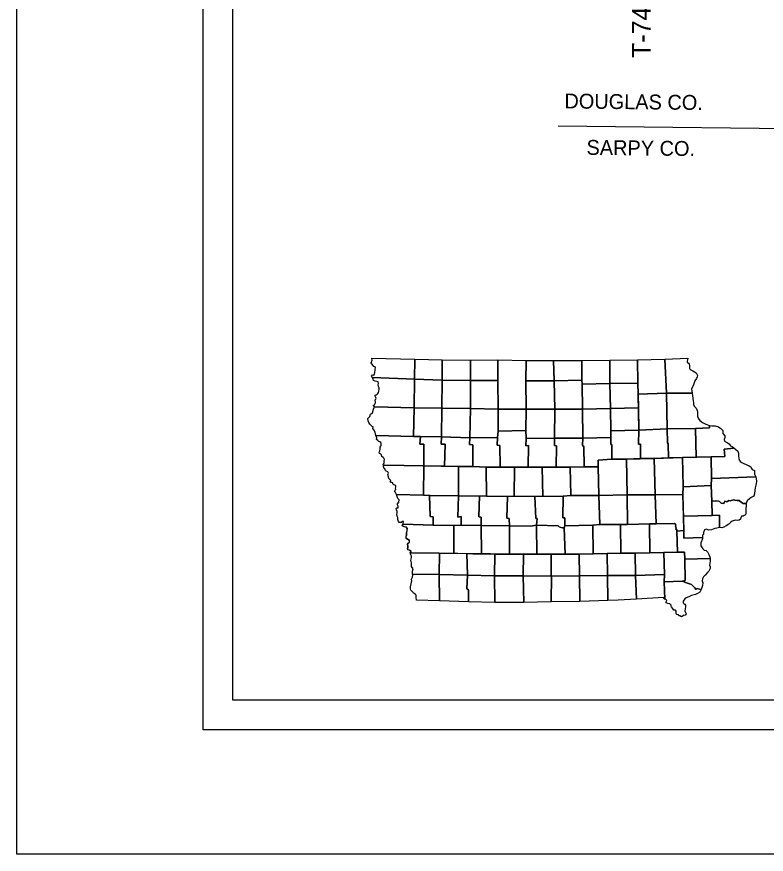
# Model space of a CAD drawing. Extents: x -132.8 to -73.3, y -60 to -26.
# Drawn here: x -132.82 to -126.79, y -60.01 to -53.27 of the extents above; entities that cross this region are included whole.
import ezdxf

# ---------------------------------------------------------------- set-up
doc = ezdxf.new("R2010")
doc.units = 0
for name, color, linetype in [('tdCoCoBndryPart', 7, 'Continuous'), ('tdCoCoBndryTxt', 7, 'Continuous'), ('tdCoFrame', 7, 'Continuous'), ('tdCoPlotFrame', 7, 'Continuous'), ('tdCoTitleBlock', 7, 'Continuous'), ('tdCoTwpRngTxt', 7, 'Continuous')]:
    doc.layers.add(name, color=color, linetype=linetype)

msp = doc.modelspace()

# ---------------------------------------------------------------- linework, layer by layer
at = {"layer": 'tdCoCoBndryPart'}
msp.add_lwpolyline([(-126.151, -54.1793), (-128.4616, -54.1519)], dxfattribs=at)
at = {"layer": 'tdCoFrame'}
for points in [[(-131.3199, -27.0113), (-77.8199, -27.0113), (-77.8199, -59.0113), (-131.3199, -59.0113)], [(-131.0799, -27.2513), (-78.0599, -27.2513), (-78.0599, -58.7713), (-131.0799, -58.7713)]]:
    msp.add_lwpolyline(points, close=True, dxfattribs=at)
at = {"layer": 'tdCoPlotFrame'}
msp.add_lwpolyline([(-132.8199, -26.0113), (-76.8199, -26.0113), (-76.8199, -60.0113), (-132.8199, -60.0113)], close=True, dxfattribs=at)
at = {"layer": 'tdCoTitleBlock'}
for points in [[(-129.9621, -56.0202), (-129.615, -56.0286), (-129.6188, -56.1889), (-129.9564, -56.1753), (-129.9634, -56.1641), (-129.9572, -56.1529), (-129.9463, -56.1549), (-129.9407, -56.1472), (-129.9372, -56.1349), (-129.9334, -56.1143), (-129.931, -56.0912), (-129.9384, -56.0884), (-129.9454, -56.0856), (-129.9542, -56.0744), (-129.9659, -56.0559), (-129.9585, -56.0363)], [(-129.615, -56.0286), (-129.3939, -56.0332), (-129.3945, -56.1956), (-129.6188, -56.1889)], [(-129.3939, -56.0332), (-129.1665, -56.036), (-129.1671, -56.1977), (-129.3945, -56.1956)], [(-129.1665, -56.036), (-128.9476, -56.0339), (-128.9481, -56.1998), (-129.1671, -56.1977)], [(-128.9476, -56.0339), (-128.7187, -56.0388), (-128.7204, -56.2016), (-128.718, -56.4287), (-128.945, -56.4287), (-128.9481, -56.1998)], [(-128.7187, -56.0388), (-128.4984, -56.0388), (-128.4944, -56.2026), (-128.7204, -56.2016)], [(-128.4984, -56.0388), (-128.271, -56.0374), (-128.2709, -56.196), (-128.4944, -56.2026)], [(-128.271, -56.0374), (-128.0467, -56.0354), (-128.0445, -56.2226), (-128.2676, -56.2296), (-128.2709, -56.196)], [(-128.0467, -56.0354), (-127.8239, -56.0319), (-127.8213, -56.2205), (-128.0445, -56.2226)], [(-127.8239, -56.0319), (-127.6021, -56.0263), (-127.5905, -56.3021), (-127.8165, -56.3087), (-127.8213, -56.2205)], [(-127.6021, -56.0263), (-127.4186, -56.0187), (-127.4211, -56.0331), (-127.4231, -56.0422), (-127.4224, -56.0513), (-127.4133, -56.0607), (-127.408, -56.0677), (-127.4037, -56.0782), (-127.4051, -56.1009), (-127.3987, -56.1111), (-127.3773, -56.1201), (-127.3632, -56.1288), (-127.3506, -56.1368), (-127.3439, -56.147), (-127.3407, -56.1595), (-127.3414, -56.1708), (-127.3487, -56.1841), (-127.3606, -56.2027), (-127.3741, -56.2409), (-127.3892, -56.2664), (-127.382, -56.2997), (-127.5905, -56.3021)], [(-129.9564, -56.1753), (-129.6188, -56.1889), (-129.6213, -56.4192), (-129.9406, -56.4097), (-129.9477, -56.4062), (-129.9491, -56.3982), (-129.94, -56.3936), (-129.9333, -56.3848), (-129.9309, -56.3754), (-129.9316, -56.3673), (-129.9355, -56.3628), (-129.9345, -56.3554), (-129.9282, -56.3502), (-129.9257, -56.3418), (-129.9303, -56.3362), (-129.9332, -56.326), (-129.9342, -56.3159), (-129.9258, -56.3138), (-129.9188, -56.3092), (-129.9129, -56.3046), (-129.9069, -56.2959), (-129.9049, -56.2839), (-129.9017, -56.2699), (-129.9018, -56.2591), (-129.9078, -56.2479), (-129.9092, -56.2332), (-129.9075, -56.2238), (-129.9107, -56.2094), (-129.9202, -56.2066), (-129.9349, -56.2042), (-129.9476, -56.1983), (-129.9504, -56.1892)], [(-129.6188, -56.1889), (-129.3945, -56.1956), (-129.3974, -56.422), (-129.6213, -56.4192)], [(-129.3945, -56.1956), (-129.1671, -56.1977), (-129.1679, -56.4245), (-129.3974, -56.422)], [(-129.1671, -56.1977), (-128.9481, -56.1998), (-128.945, -56.4287), (-129.1679, -56.4245)], [(-128.7204, -56.2016), (-128.4944, -56.2026), (-128.4892, -56.4305), (-128.718, -56.4287)], [(-128.4944, -56.2026), (-128.2709, -56.196), (-128.2676, -56.2296), (-128.2649, -56.4294), (-128.4892, -56.4305)], [(-128.2676, -56.2296), (-128.0445, -56.2226), (-128.0397, -56.4249), (-128.2649, -56.4294)], [(-128.0445, -56.2226), (-127.8213, -56.2205), (-127.8165, -56.3087), (-127.8151, -56.42), (-128.0397, -56.4249)], [(-127.8165, -56.3087), (-127.5905, -56.3021), (-127.5844, -56.5887), (-127.8114, -56.5981)], [(-127.5905, -56.3021), (-127.382, -56.2997), (-127.3752, -56.3637), (-127.372, -56.3791), (-127.373, -56.3921), (-127.3663, -56.4064), (-127.3512, -56.4228), (-127.3424, -56.4392), (-127.3392, -56.4542), (-127.3402, -56.4693), (-127.3387, -56.4861), (-127.3345, -56.5022), (-127.3207, -56.521), (-127.2986, -56.5378), (-127.2715, -56.5496), (-127.242, -56.5607), (-127.2419, -56.5789), (-127.357, -56.5863), (-127.5844, -56.5887)], [(-129.9406, -56.4097), (-129.6213, -56.4192), (-129.6252, -56.6492), (-129.9298, -56.6407), (-129.9341, -56.6148), (-129.9447, -56.597), (-129.9528, -56.5865), (-129.9497, -56.5728), (-129.9584, -56.568), (-129.9764, -56.5502), (-129.9863, -56.5372), (-129.9905, -56.5229), (-129.993, -56.5058), (-129.9867, -56.4966), (-129.9783, -56.4886), (-129.9714, -56.469), (-129.9567, -56.4584), (-129.9487, -56.429)], [(-129.6213, -56.4192), (-129.3974, -56.422), (-129.4006, -56.6524), (-129.5694, -56.6494), (-129.6252, -56.6492)], [(-129.3974, -56.422), (-129.1679, -56.4245), (-129.1714, -56.659), (-129.4006, -56.6524)], [(-129.1679, -56.4245), (-128.945, -56.4287), (-128.9431, -56.6055), (-128.9486, -56.658), (-129.1714, -56.659)], [(-128.945, -56.4287), (-128.718, -56.4287), (-128.7214, -56.6013), (-128.9431, -56.6055)], [(-128.718, -56.4287), (-128.4892, -56.4305), (-128.4906, -56.665), (-128.7177, -56.6653), (-128.7214, -56.6013)], [(-128.4892, -56.4305), (-128.2649, -56.4294), (-128.2629, -56.6639), (-128.4899, -56.6643)], [(-128.2649, -56.4294), (-128.0397, -56.4249), (-128.0381, -56.6044), (-128.0373, -56.658), (-128.2629, -56.6639)], [(-128.0397, -56.4249), (-127.8151, -56.42), (-127.8114, -56.5981), (-128.0381, -56.6044)], [(-128.9431, -56.6055), (-128.7214, -56.6013), (-128.7177, -56.6653), (-128.7217, -56.7238), (-128.7, -56.7209), (-128.7016, -56.8952), (-128.8142, -56.8956), (-128.9279, -56.8931), (-128.9302, -56.7216), (-128.9516, -56.7182), (-128.9486, -56.658)], [(-128.0381, -56.6044), (-127.8114, -56.5981), (-127.8153, -56.7105), (-127.7995, -56.7112), (-127.7992, -56.8267), (-127.9118, -56.8316), (-128.029, -56.8316), (-128.0294, -56.715), (-128.0385, -56.7147), (-128.0373, -56.658)], [(-127.8114, -56.5981), (-127.5844, -56.5887), (-127.5813, -56.7), (-127.5746, -56.7094), (-127.5722, -56.8225), (-127.688, -56.826), (-127.7992, -56.8267), (-127.7995, -56.7112), (-127.8153, -56.7105)], [(-127.5844, -56.5887), (-127.357, -56.5863), (-127.3494, -56.8155), (-127.5722, -56.8225), (-127.5746, -56.7094), (-127.5813, -56.7)], [(-127.357, -56.5863), (-127.2419, -56.5789), (-127.242, -56.5607), (-127.223, -56.5634), (-127.1964, -56.5627), (-127.1693, -56.5713), (-127.151, -56.586), (-127.1366, -56.6006), (-127.1369, -56.6258), (-127.1189, -56.645), (-127.1203, -56.6587), (-127.1259, -56.6741), (-127.1227, -56.687), (-127.097, -56.7003), (-127.0858, -56.7086), (-127.0738, -56.724), (-127.0601, -56.7309), (-127.0446, -56.7442), (-127.126, -56.7518), (-127.1206, -56.8113), (-127.2308, -56.8137), (-127.3494, -56.8155)], [(-129.9298, -56.6407), (-129.6252, -56.6492), (-129.5694, -56.6494), (-129.5762, -56.7106), (-129.5426, -56.7102), (-129.5421, -56.8859), (-129.8607, -56.8813), (-129.8667, -56.8855), (-129.8709, -56.8743), (-129.8636, -56.8652), (-129.8601, -56.8606), (-129.8608, -56.8522), (-129.8612, -56.8421), (-129.8594, -56.8361), (-129.8619, -56.826), (-129.8711, -56.8197), (-129.8806, -56.811), (-129.8841, -56.7977), (-129.8908, -56.7904), (-129.8985, -56.7851), (-129.9031, -56.7767), (-129.9007, -56.7701), (-129.8972, -56.7645), (-129.8951, -56.7533), (-129.893, -56.7428), (-129.8938, -56.7347), (-129.8889, -56.7277), (-129.8868, -56.7203), (-129.8868, -56.7063), (-129.8897, -56.6973), (-129.896, -56.6938), (-129.9051, -56.6886), (-129.9136, -56.6816), (-129.9227, -56.6732), (-129.9206, -56.6592)], [(-129.5694, -56.6494), (-129.4006, -56.6524), (-129.4029, -56.7119), (-129.372, -56.7111), (-129.3768, -56.8889), (-129.5421, -56.8859), (-129.5426, -56.7102), (-129.5762, -56.7106)], [(-129.4006, -56.6524), (-129.1714, -56.659), (-129.1748, -56.7143), (-129.1495, -56.7156), (-129.1483, -56.8903), (-129.2624, -56.8913), (-129.3768, -56.8889), (-129.372, -56.7111), (-129.4029, -56.7119)], [(-129.1714, -56.659), (-128.9486, -56.658), (-128.9516, -56.7182), (-128.9302, -56.7216), (-128.9279, -56.8931), (-129.0402, -56.8959), (-129.1483, -56.8903), (-129.1495, -56.7156), (-129.1748, -56.7143)], [(-128.7177, -56.6653), (-128.4899, -56.6643), (-128.4905, -56.7224), (-128.474, -56.7244), (-128.4773, -56.8963), (-128.5893, -56.8977), (-128.7016, -56.8952), (-128.7, -56.7209), (-128.7217, -56.7238)], [(-128.4899, -56.6643), (-128.2629, -56.6639), (-128.2645, -56.721), (-128.2536, -56.729), (-128.2521, -56.8935), (-128.365, -56.8963), (-128.4773, -56.8963), (-128.474, -56.7244), (-128.4905, -56.7224)], [(-128.2629, -56.6639), (-128.0373, -56.658), (-128.0385, -56.7147), (-128.0294, -56.715), (-128.029, -56.8316), (-128.1382, -56.8399), (-128.1387, -56.8935), (-128.2521, -56.8935), (-128.2536, -56.729), (-128.2645, -56.721)], [(-127.2308, -56.8137), (-127.1206, -56.8113), (-127.126, -56.7518), (-127.0446, -56.7442), (-127.0351, -56.7526), (-127.0147, -56.7669), (-127.0094, -56.784), (-127.0097, -56.8043), (-127.0072, -56.826), (-127.0026, -56.8435), (-126.991, -56.8574), (-126.9231, -56.8845), (-126.9101, -56.8943), (-126.9059, -56.9072), (-126.8996, -56.9153), (-126.8816, -56.9229), (-126.8808, -56.9519), (-126.8692, -56.9754), (-127.2278, -56.9877)], [(-127.4602, -56.8193), (-127.2308, -56.8137), (-127.2278, -56.9877), (-127.2294, -57.0437), (-127.4543, -57.0552)], [(-129.8667, -56.8855), (-129.8607, -56.8813), (-129.5421, -56.8859), (-129.5442, -57.1225), (-129.7635, -57.1176), (-129.7685, -57.1057), (-129.7731, -57.0942), (-129.7787, -57.0872), (-129.7689, -57.0752), (-129.7704, -57.0665), (-129.7669, -57.0556), (-129.7669, -57.0455), (-129.7753, -57.0406), (-129.7753, -57.0406), (-129.7848, -57.0375), (-129.7912, -57.0305), (-129.7915, -57.0218), (-129.801, -57.0211), (-129.808, -57.0211), (-129.8133, -57.0148), (-129.8081, -57.0036), (-129.8172, -56.9963), (-129.8257, -56.9876), (-129.8285, -56.9736), (-129.8314, -56.955), (-129.8282, -56.9435), (-129.8282, -56.9435), (-129.8335, -56.9347), (-129.8458, -56.9299), (-129.8508, -56.9236), (-129.8554, -56.9093), (-129.8638, -56.9044)], [(-128.1382, -56.8399), (-128.029, -56.8316), (-127.9118, -56.8316), (-127.9058, -57.1199), (-128.1338, -57.1248), (-128.1387, -56.8935)], [(-127.9118, -56.8316), (-127.688, -56.826), (-127.6794, -57.1203), (-127.9058, -57.1199)], [(-127.688, -56.826), (-127.4602, -56.8193), (-127.4543, -57.0552), (-127.4566, -57.1154), (-127.6794, -57.1203)], [(-129.5421, -56.8859), (-129.2624, -56.8913), (-129.2642, -57.1279), (-129.4909, -57.1248), (-129.5442, -57.1225)], [(-129.2624, -56.8913), (-129.1483, -56.8903), (-129.0402, -56.8959), (-129.0385, -57.1294), (-129.2642, -57.1279)], [(-129.0402, -56.8959), (-128.8142, -56.8956), (-128.8146, -57.1304), (-128.8694, -57.132), (-129.0385, -57.1294)], [(-128.8142, -56.8956), (-128.5893, -56.8977), (-128.5858, -57.1322), (-128.6479, -57.1327), (-128.8146, -57.1304)], [(-128.5893, -56.8977), (-128.365, -56.8963), (-128.3591, -57.1252), (-128.4216, -57.1303), (-128.5858, -57.1322)], [(-128.365, -56.8963), (-128.2521, -56.8935), (-128.1387, -56.8935), (-128.1338, -57.1248), (-128.3591, -57.1252)], [(-127.2278, -56.9877), (-126.8692, -56.9754), (-126.8671, -56.9887), (-126.8656, -57.0107), (-126.8669, -57.0286), (-126.8704, -57.0405), (-126.8753, -57.0615), (-126.8791, -57.0818), (-126.88, -57.1119), (-126.8874, -57.1301), (-126.907, -57.1417), (-126.9224, -57.1502), (-126.9388, -57.1663), (-126.9451, -57.1817), (-126.9469, -57.1895), (-126.9721, -57.1878), (-126.989, -57.1787), (-127.0038, -57.1651), (-127.0203, -57.1641), (-127.0382, -57.1624), (-127.0494, -57.1586), (-127.0775, -57.1671), (-127.0883, -57.1654), (-127.1038, -57.1745), (-127.1094, -57.1714), (-127.1185, -57.169), (-127.129, -57.1883), (-127.1504, -57.1862), (-127.1631, -57.1716), (-127.1915, -57.1675), (-127.2248, -57.1711), (-127.2294, -57.0437)], [(-127.4543, -57.0552), (-127.2294, -57.0437), (-127.2248, -57.1711), (-127.2207, -57.2851), (-127.4536, -57.2897), (-127.4566, -57.1154)], [(-129.7635, -57.1176), (-129.5442, -57.1225), (-129.4973, -57.1247), (-129.4921, -57.2938), (-129.4683, -57.2952), (-129.4686, -57.3625), (-129.7086, -57.3562), (-129.7068, -57.3323), (-129.7145, -57.3341), (-129.725, -57.3422), (-129.7401, -57.3419), (-129.7475, -57.3324), (-129.7517, -57.317), (-129.7511, -57.3002), (-129.7574, -57.2915), (-129.7592, -57.2786), (-129.7561, -57.2649), (-129.7586, -57.252), (-129.7621, -57.2401), (-129.7664, -57.2296), (-129.7604, -57.2226), (-129.7499, -57.2225), (-129.7503, -57.2113), (-129.7542, -57.2008), (-129.7539, -57.1924), (-129.743, -57.1788), (-129.7403, -57.1606), (-129.7512, -57.148)], [(-129.4973, -57.1247), (-129.2642, -57.1279), (-129.2682, -57.2981), (-129.243, -57.2945), (-129.2417, -57.3627), (-129.3014, -57.3664), (-129.4686, -57.3625), (-129.4683, -57.2952), (-129.4921, -57.2938)], [(-129.2642, -57.1279), (-129.0954, -57.1278), (-129.0987, -57.2958), (-129.0808, -57.2999), (-129.0799, -57.3657), (-129.2417, -57.3627), (-129.243, -57.2945), (-129.2682, -57.2981)], [(-129.0954, -57.1278), (-129.0385, -57.1294), (-128.8694, -57.132), (-128.8752, -57.3081), (-128.8569, -57.309), (-128.8529, -57.3689), (-129.0799, -57.3657), (-129.0808, -57.2999), (-129.0987, -57.2958)], [(-128.8694, -57.132), (-128.8146, -57.1304), (-128.6479, -57.1327), (-128.6422, -57.3094), (-128.6316, -57.3108), (-128.6357, -57.3633), (-128.6834, -57.3705), (-128.8529, -57.3689), (-128.8569, -57.309), (-128.8752, -57.3081)], [(-128.6422, -57.3094), (-128.6479, -57.1327), (-128.4216, -57.1303), (-128.4225, -57.3035), (-128.4067, -57.3052), (-128.4076, -57.3686), (-128.4117, -57.3833), (-128.4272, -57.3851), (-128.4405, -57.383), (-128.4535, -57.3757), (-128.4606, -57.3673), (-128.6357, -57.3633), (-128.6316, -57.3108)], [(-128.4216, -57.1303), (-128.3591, -57.1252), (-128.1338, -57.1248), (-128.1248, -57.359), (-128.183, -57.363), (-128.4076, -57.3686), (-128.4067, -57.3052), (-128.4225, -57.3035)], [(-128.1338, -57.1248), (-127.9058, -57.1199), (-127.9019, -57.3569), (-128.1248, -57.359)], [(-127.9058, -57.1199), (-127.6794, -57.1203), (-127.6731, -57.3534), (-127.7268, -57.3521), (-127.9019, -57.3569)], [(-127.6794, -57.1203), (-127.4566, -57.1154), (-127.4505, -57.4059), (-127.5056, -57.4103), (-127.5053, -57.4008), (-127.513, -57.3966), (-127.5116, -57.3868), (-127.5173, -57.3725), (-127.5145, -57.3602), (-127.5177, -57.3547), (-127.5258, -57.3487), (-127.6731, -57.3534)], [(-127.2248, -57.1711), (-127.1915, -57.1675), (-127.1733, -57.1684), (-127.1631, -57.1716), (-127.1504, -57.1862), (-127.129, -57.1883), (-127.1185, -57.169), (-127.1094, -57.1714), (-127.1038, -57.1745), (-127.0883, -57.1654), (-127.0775, -57.1671), (-127.0494, -57.1586), (-127.0382, -57.1624), (-127.0203, -57.1641), (-127.0038, -57.1651), (-126.989, -57.1787), (-126.9721, -57.1878), (-126.9469, -57.1895), (-126.9482, -57.2084), (-126.9513, -57.2308), (-126.9498, -57.2675), (-126.9526, -57.2791), (-126.9638, -57.2861), (-126.9729, -57.2896), (-126.981, -57.2897), (-126.9866, -57.2911), (-126.9911, -57.3037), (-126.9946, -57.3142), (-127.0037, -57.3233), (-127.0184, -57.3255), (-127.0367, -57.3241), (-127.0605, -57.3312), (-127.0745, -57.3407), (-127.0882, -57.3551), (-127.1095, -57.3685), (-127.1281, -57.3804), (-127.1449, -57.3833), (-127.1632, -57.3826), (-127.1631, -57.2822), (-127.2207, -57.2851)], [(-127.4536, -57.2897), (-127.2207, -57.2851), (-127.1631, -57.2822), (-127.1632, -57.3826), (-127.1832, -57.3865), (-127.1997, -57.3894), (-127.2137, -57.3947), (-127.228, -57.4017), (-127.2473, -57.4046), (-127.2705, -57.3966), (-127.2835, -57.4019), (-127.2915, -57.4226), (-127.2918, -57.4345), (-127.2985, -57.4429), (-127.2995, -57.4625), (-127.4503, -57.4671), (-127.4505, -57.4059)], [(-127.9588, -57.3585), (-127.9019, -57.3569), (-127.7268, -57.3521), (-127.7223, -57.5863), (-127.8413, -57.5891), (-127.9574, -57.5891)], [(-127.7268, -57.3521), (-127.6731, -57.3534), (-127.5258, -57.3487), (-127.5177, -57.3547), (-127.5145, -57.3602), (-127.5173, -57.3725), (-127.5138, -57.3802), (-127.5116, -57.3868), (-127.513, -57.3966), (-127.5053, -57.4008), (-127.5056, -57.4103), (-127.4995, -57.5796), (-127.6104, -57.5824), (-127.7223, -57.5863)], [(-129.7086, -57.3562), (-129.4686, -57.3625), (-129.3014, -57.3664), (-129.3003, -57.5918), (-129.4181, -57.5894), (-129.6515, -57.5863), (-129.6462, -57.5701), (-129.6702, -57.5621), (-129.6748, -57.5543), (-129.671, -57.5452), (-129.6714, -57.5329), (-129.6749, -57.5171), (-129.67, -57.5076), (-129.6584, -57.4998), (-129.6577, -57.488), (-129.6849, -57.4698), (-129.6861, -57.4549), (-129.6812, -57.4422), (-129.6812, -57.4243), (-129.6774, -57.4074), (-129.6759, -57.4007), (-129.6767, -57.3901), (-129.6845, -57.38), (-129.7015, -57.3769), (-129.718, -57.3681)], [(-129.7086, -57.3562), (-129.4686, -57.3625), (-129.3014, -57.3664), (-129.3004, -57.5908), (-129.6422, -57.5845), (-129.6499, -57.5852), (-129.6447, -57.5691), (-129.6581, -57.5635), (-129.6686, -57.5611), (-129.6732, -57.5534), (-129.6693, -57.5443), (-129.6697, -57.532), (-129.6733, -57.5163), (-129.6684, -57.5068), (-129.6568, -57.4991), (-129.6569, -57.4858), (-129.6699, -57.4781), (-129.6839, -57.4677), (-129.6843, -57.4544), (-129.6795, -57.4418), (-129.6795, -57.4239), (-129.6757, -57.4071), (-129.675, -57.39), (-129.6828, -57.3798), (-129.6996, -57.3767), (-129.7162, -57.368), (-129.712, -57.3582)], [(-129.3014, -57.3664), (-129.2417, -57.3627), (-129.0799, -57.3657), (-129.0798, -57.5939), (-129.1495, -57.5927), (-129.2678, -57.5917), (-129.3004, -57.5908)], [(-129.0799, -57.3657), (-128.8529, -57.3689), (-128.854, -57.5953), (-129.0053, -57.5951), (-129.0798, -57.5939)], [(-128.8529, -57.3689), (-128.6834, -57.3705), (-128.6357, -57.3633), (-128.6343, -57.5954), (-128.854, -57.5953)], [(-128.6357, -57.3633), (-128.4606, -57.3673), (-128.4535, -57.3757), (-128.4272, -57.3851), (-128.4117, -57.3833), (-128.4052, -57.5971), (-128.6343, -57.5954)], [(-128.4076, -57.3686), (-128.183, -57.363), (-128.1799, -57.5947), (-128.4052, -57.5971), (-128.4117, -57.3833)], [(-128.183, -57.363), (-128.1248, -57.359), (-127.9588, -57.3585), (-127.9574, -57.5891), (-128.1799, -57.5947)], [(-127.5056, -57.4103), (-127.4505, -57.4059), (-127.4503, -57.4671), (-127.2995, -57.4625), (-127.3005, -57.4723), (-127.3137, -57.5066), (-127.3119, -57.5287), (-127.2978, -57.5531), (-127.2848, -57.5653), (-127.2693, -57.5681), (-127.2591, -57.5779), (-127.2482, -57.5999), (-127.2482, -57.5999), (-127.2404, -57.6177), (-127.2379, -57.631), (-127.4404, -57.6362), (-127.4441, -57.5805), (-127.4995, -57.5796)], [(-129.6499, -57.5852), (-129.6422, -57.5845), (-129.4176, -57.5883), (-129.4189, -57.7588), (-129.6336, -57.7566), (-129.634, -57.7472), (-129.6337, -57.7332), (-129.6299, -57.7157), (-129.6422, -57.6954), (-129.643, -57.6814), (-129.6413, -57.6653), (-129.6452, -57.6566), (-129.6487, -57.6492), (-129.6442, -57.6342), (-129.6414, -57.6233), (-129.6432, -57.6121), (-129.6464, -57.6023), (-129.6503, -57.5925)], [(-129.4176, -57.5883), (-129.1971, -57.5922), (-129.1915, -57.7644), (-129.4189, -57.7588)], [(-129.1971, -57.5922), (-129.1495, -57.5927), (-129.0798, -57.5939), (-129.0053, -57.5951), (-128.9718, -57.5952), (-128.9728, -57.7697), (-129.1915, -57.7644)], [(-128.9718, -57.5952), (-128.741, -57.5964), (-128.7426, -57.7721), (-128.9728, -57.7697)], [(-128.741, -57.5964), (-128.5171, -57.5982), (-128.5177, -57.7725), (-128.7426, -57.7721)], [(-128.5171, -57.5982), (-128.2911, -57.5968), (-128.2896, -57.7711), (-128.5177, -57.7725)], [(-128.2911, -57.5968), (-128.0662, -57.5919), (-128.0629, -57.7676), (-128.2896, -57.7711)], [(-128.0662, -57.5919), (-127.9574, -57.5891), (-127.8413, -57.5891), (-127.839, -57.7676), (-128.0629, -57.7676)], [(-127.8413, -57.5891), (-127.7223, -57.5863), (-127.6104, -57.5824), (-127.606, -57.7599), (-127.839, -57.7676)], [(-127.6104, -57.5824), (-127.4995, -57.5796), (-127.4441, -57.5805), (-127.4404, -57.6362), (-127.4403, -57.8084), (-127.4599, -57.8126), (-127.6069, -57.8187), (-127.606, -57.7599)], [(-127.4404, -57.6362), (-127.2379, -57.631), (-127.2368, -57.6527), (-127.2396, -57.6702), (-127.2444, -57.686), (-127.2374, -57.6975), (-127.2373, -57.7125), (-127.2485, -57.7325), (-127.259, -57.7431), (-127.2783, -57.7645), (-127.2905, -57.7796), (-127.2999, -57.7943), (-127.3034, -57.8115), (-127.297, -57.8268), (-127.2991, -57.8478), (-127.3102, -57.8818), (-127.3232, -57.877), (-127.3418, -57.8739), (-127.3516, -57.8805), (-127.3601, -57.8673), (-127.3893, -57.8408), (-127.4356, -57.8248), (-127.4599, -57.8126), (-127.4403, -57.8084)], [(-129.6336, -57.7566), (-129.4189, -57.7588), (-129.4158, -57.9726), (-129.6008, -57.9662), (-129.604, -57.9452), (-129.604, -57.9277), (-129.6111, -57.9204), (-129.6216, -57.9127), (-129.6336, -57.9001), (-129.6477, -57.8869), (-129.6512, -57.8746), (-129.6509, -57.8582), (-129.6443, -57.8344), (-129.6405, -57.812), (-129.6416, -57.7983), (-129.6336, -57.7815), (-129.6315, -57.7622)], [(-129.4189, -57.7588), (-129.1915, -57.7644), (-129.1961, -57.8743), (-129.1838, -57.8834), (-129.1821, -57.9814), (-129.4158, -57.9726)], [(-129.1915, -57.7644), (-128.9728, -57.7697), (-128.9715, -57.9846), (-129.1821, -57.9814), (-129.1838, -57.8834), (-129.1961, -57.8743)], [(-128.9728, -57.7697), (-128.7426, -57.7721), (-128.7382, -57.9866), (-128.9715, -57.9846)], [(-128.7426, -57.7721), (-128.5138, -57.7711), (-128.5174, -57.9814), (-128.7382, -57.9866)], [(-128.5138, -57.7711), (-128.2896, -57.7711), (-128.2858, -57.9765), (-128.5174, -57.9814)], [(-128.2896, -57.7711), (-128.0629, -57.7676), (-128.062, -57.9685), (-128.2858, -57.9765)], [(-128.0629, -57.7676), (-127.839, -57.7676), (-127.8316, -57.9593), (-127.9781, -57.9675), (-128.062, -57.9685)], [(-127.839, -57.7676), (-127.606, -57.7599), (-127.6069, -57.8187), (-127.6023, -57.9576), (-127.6146, -57.9458), (-127.8316, -57.9593)], [(-127.6069, -57.8187), (-127.4599, -57.8126), (-127.4356, -57.8248), (-127.3893, -57.8408), (-127.3601, -57.8673), (-127.3516, -57.8805), (-127.3418, -57.8739), (-127.3232, -57.877), (-127.3102, -57.8818), (-127.3221, -57.9011), (-127.3399, -57.9141), (-127.3561, -57.9198), (-127.3869, -57.9304), (-127.4101, -57.9392), (-127.43, -57.9469), (-127.4419, -57.9564), (-127.4552, -57.9757), (-127.4545, -57.9869), (-127.4489, -57.9942), (-127.4418, -57.9995), (-127.4362, -58.0068), (-127.4361, -58.0201), (-127.4396, -58.0369), (-127.441, -58.0516), (-127.4371, -58.0667), (-127.4321, -58.0771), (-127.4335, -58.0849), (-127.4402, -58.0877), (-127.4517, -58.0902), (-127.463, -58.0968), (-127.4686, -58.1018), (-127.4819, -58.092), (-127.491, -58.092), (-127.4921, -58.0843), (-127.5048, -58.0823), (-127.5114, -58.0774), (-127.5104, -58.0651), (-127.5115, -58.0546), (-127.5178, -58.0484), (-127.5298, -58.0484), (-127.5358, -58.04), (-127.541, -58.0302), (-127.5502, -58.0215), (-127.5527, -58.0138), (-127.5516, -58.0072), (-127.5618, -57.9967), (-127.5783, -57.9932), (-127.5906, -57.987), (-127.5907, -57.9789), (-127.5865, -57.9695), (-127.5935, -57.9611), (-127.6023, -57.9576)]]:
    msp.add_lwpolyline(points, close=True, dxfattribs=at)

# ---------------------------------------------------------------- texts
at = {"layer": 'tdCoCoBndryTxt'}
for s, p in [('DOUGLAS CO.', (-128.4117, -54.0093)), ('SARPY CO.', (-128.2339, -54.3827))]:
    msp.add_text(s, height=0.12, rotation=359.3216, dxfattribs=at).set_placement(p)
at = {"layer": 'tdCoTwpRngTxt'}
msp.add_text('T-74N', height=0.15, rotation=89.90553, dxfattribs=at).set_placement((-127.7163, -53.603))

doc.saveas('drawing.dxf')
